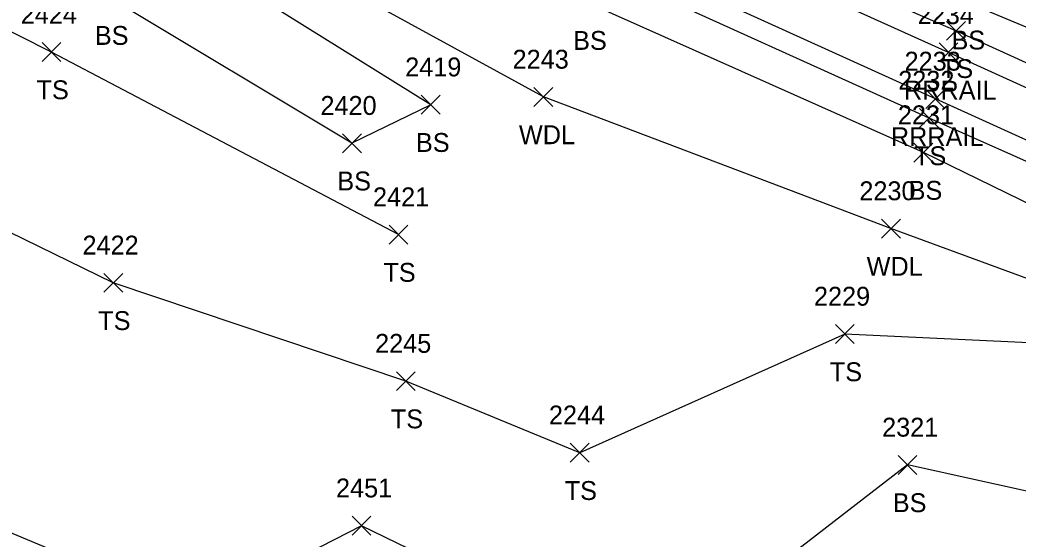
# Model space of a CAD drawing. Extents: x 1599569 to 1610055, y 642560 to 647860.
# Drawn here: x 1601397.5 to 1601503.2, y 647129.7 to 647184.7 of the extents above; entities that cross this region are included whole.
import ezdxf

# ---------------------------------------------------------------- set-up
doc = ezdxf.new("R2010")
doc.units = 0
for name, color, linetype in [('L_A', 7, 'Continuous'), ('L_I', 7, 'Continuous'), ('L_TIC', 7, 'Continuous'), ('LAWA', 7, 'Continuous'), ('LELB', 7, 'Continuous'), ('R_A', 7, 'Continuous'), ('R_I', 7, 'Continuous'), ('R_TIC', 7, 'Continuous'), ('RR', 7, 'Continuous')]:
    doc.layers.add(name, color=color, linetype=linetype)

msp = doc.modelspace()

# ---------------------------------------------------------------- linework, layer by layer
at = {"layer": 'L_TIC'}
for points in [[(1601495.65, 647182.57), (1601497.65, 647184.57)], [(1601497.65, 647182.57), (1601495.65, 647184.57)], [(1601399.83, 647180.32), (1601401.83, 647182.32)], [(1601401.83, 647180.32), (1601399.83, 647182.32)], [(1601440, 647174.74), (1601442, 647176.74)], [(1601442, 647174.74), (1601440, 647176.74)], [(1601440, 647174.74), (1601442, 647176.74)], [(1601442, 647174.74), (1601440, 647176.74)], [(1601451.94, 647175.56), (1601453.94, 647177.56)], [(1601453.94, 647175.56), (1601451.94, 647177.56)], [(1601492.8, 647173.33), (1601494.8, 647175.33)], [(1601494.8, 647173.33), (1601492.8, 647175.33)], [(1601431.66, 647170.66), (1601433.66, 647172.66)], [(1601433.66, 647170.66), (1601431.66, 647172.66)], [(1601492.2, 647169.67), (1601494.2, 647171.67)], [(1601494.2, 647169.67), (1601492.2, 647171.67)], [(1601436.59, 647160.98), (1601438.59, 647162.98)], [(1601438.59, 647160.98), (1601436.59, 647162.98)], [(1601488.77, 647161.62), (1601490.77, 647163.62)], [(1601490.77, 647161.62), (1601488.77, 647163.62)], [(1601406.37, 647155.87), (1601408.37, 647157.87)], [(1601408.37, 647155.87), (1601406.37, 647157.87)], [(1601483.88, 647150.45), (1601485.88, 647152.45)], [(1601485.88, 647150.45), (1601483.88, 647152.45)], [(1601437.37, 647145.46), (1601439.37, 647147.46)], [(1601439.37, 647145.46), (1601437.37, 647147.46)], [(1601455.79, 647137.87), (1601457.79, 647139.87)], [(1601457.79, 647137.87), (1601455.79, 647139.87)], [(1601490.52, 647136.58), (1601492.52, 647138.58)], [(1601492.52, 647136.58), (1601490.52, 647138.58)], [(1601432.67, 647130.14), (1601434.67, 647132.14)], [(1601434.67, 647130.14), (1601432.67, 647132.14)]]:
    msp.add_lwpolyline(points, dxfattribs=at)
at = {"layer": 'LAWA'}
msp.add_lwpolyline([(1601543.96, 647141.4), (1601525.42, 647149.53), (1601489.77, 647162.62), (1601452.94, 647176.56), (1601417.12, 647196.22), (1601382.92, 647211.21), (1601340.76, 647217.08), (1601306.6, 647220.69), (1601276.84, 647227.54)], dxfattribs=at)
at = {"layer": 'LELB'}
for points in [[(1601782.46, 647059.4), (1601738.77, 647079.33), (1601690.4, 647099.93), (1601647.7, 647120.25), (1601610.06, 647137.74), (1601571.92, 647154.07), (1601536.97, 647170.25), (1601497.74, 647186.59), (1601465.75, 647201.27), (1601394.71, 647231.37), (1601362.21, 647245.73), (1601329.86, 647260.18), (1601292.61, 647278.06)], [(1601779.91, 647055.75), (1601736.46, 647075.12), (1601688.29, 647096.71), (1601645.48, 647116.21), (1601608.08, 647132.73), (1601569.65, 647149.89), (1601535.69, 647165.81), (1601496.65, 647183.57), (1601464.02, 647197.75), (1601393.37, 647229.99), (1601361.18, 647244.46), (1601329.08, 647258.95), (1601292.39, 647275.61)], [(1601775.59, 647047.17), (1601732.38, 647067.08), (1601683.7, 647088.91), (1601643.36, 647107.34), (1601603.44, 647124.91), (1601567.99, 647141.64), (1601531.27, 647157.66), (1601493.8, 647174.33), (1601459.44, 647189.9), (1601386.61, 647223.07), (1601358.08, 647235.63), (1601326.17, 647250.65), (1601291.06, 647266.1)], [(1601773.31, 647043.55), (1601729.79, 647062.38), (1601680.12, 647084.11), (1601641.71, 647102.62), (1601602.29, 647120.48), (1601566.23, 647136.75), (1601528.31, 647153.55), (1601493.2, 647170.67), (1601457.65, 647186.55), (1601384.33, 647220.55), (1601356.62, 647233.9), (1601324.87, 647247.72), (1601290.33, 647262.4)], [(1601441, 647175.74), (1601414.25, 647192.43), (1601380.27, 647208.07), (1601340.76, 647217.08)], [(1601441, 647175.74), (1601432.66, 647171.66), (1601406.98, 647187.08), (1601375.36, 647201.94), (1601340.76, 647217.08)], [(1601437.59, 647161.98), (1601400.83, 647181.32), (1601369.9, 647196.94), (1601340.76, 647217.08)], [(1601525.42, 647149.53), (1601484.88, 647151.45), (1601456.79, 647138.87), (1601438.37, 647146.46), (1601407.37, 647156.87), (1601391.65, 647164.55), (1601361.3, 647186.25), (1601336.82, 647204.88)], [(1601786.42, 647020.74), (1601762.67, 647028.99), (1601751.67, 647030.89), (1601732.96, 647040.23), (1601698.47, 647053.93), (1601685.61, 647056.76), (1601664.03, 647070.39), (1601639.36, 647075.33), (1601612.31, 647092.93), (1601584.19, 647104.61), (1601538.73, 647126.26), (1601520.13, 647131.26), (1601491.52, 647137.58), (1601474.1, 647124.14), (1601450.02, 647123.17), (1601433.67, 647131.14), (1601416.15, 647122.17), (1601393.03, 647131.84), (1601363.94, 647128.32), (1601336.7, 647135.49), (1601311.97, 647149.61), (1601287.9, 647169.52)]]:
    msp.add_lwpolyline(points, dxfattribs=at)
at = {"layer": 'R_TIC'}
for points in [[(1601494.86, 647180.28), (1601496.86, 647182.28)], [(1601496.86, 647180.28), (1601494.86, 647182.28)], [(1601493.47, 647175.35), (1601495.47, 647177.35)], [(1601495.47, 647175.35), (1601493.47, 647177.35)]]:
    msp.add_lwpolyline(points, dxfattribs=at)
at = {"layer": 'RR'}
for points in [[(1601779.12, 647053.17), (1601735.09, 647073.16), (1601687.31, 647094.74), (1601644.71, 647114), (1601606.95, 647130.88), (1601569.09, 647148.12), (1601534.47, 647163.75), (1601495.86, 647181.28), (1601463.02, 647196.09), (1601391.8, 647228.12), (1601360.22, 647242.53), (1601328.26, 647256.93), (1601292.48, 647273.14)], [(1601776.78, 647048.8), (1601733.22, 647068.55), (1601684.48, 647090.67), (1601642.81, 647109.31), (1601604.47, 647126.66), (1601567.91, 647143.17), (1601532.13, 647159.27), (1601494.47, 647176.35), (1601460.57, 647191.75), (1601388.17, 647224.38), (1601357.5, 647238.3), (1601326.5, 647252.29), (1601291.28, 647268.22)]]:
    msp.add_lwpolyline(points, dxfattribs=at)

# ---------------------------------------------------------------- texts
at = {"layer": 'L_A'}
for s, p in [('BS', (1601405.42, 647182.08)), ('BS', (1601456.09, 647181.55)), ('BS', (1601496.18, 647181.59)), ('TS', (1601495.06, 647178.57)), ('TS', (1601399.24, 647176.32)), ('WDL', (1601450.35, 647171.56)), ('BS', (1601439.44, 647170.74)), ('BS', (1601439.44, 647170.74)), ('TS', (1601492.21, 647169.33)), ('BS', (1601431.11, 647166.66)), ('BS', (1601491.64, 647165.67)), ('TS', (1601435.99, 647156.98)), ('WDL', (1601487.19, 647157.62)), ('TS', (1601405.78, 647151.87)), ('TS', (1601483.29, 647146.45)), ('TS', (1601436.78, 647141.46)), ('TS', (1601455.2, 647133.87)), ('BS', (1601489.96, 647132.58))]:
    msp.add_text(s, height=2, dxfattribs=at).set_placement(p)
at = {"layer": 'L_I'}
for s, p in [('2424', (1601397.57, 647184.32)), ('2243', (1601449.68, 647179.56)), ('2419', (1601438.3, 647178.74)), ('2419', (1601438.3, 647178.74)), ('2232', (1601490.54, 647177.33)), ('2420', (1601429.32, 647174.66)), ('2231', (1601490.5, 647173.67)), ('2230', (1601486.42, 647165.62)), ('2421', (1601434.89, 647164.98)), ('2422', (1601404.11, 647159.87)), ('2229', (1601481.61, 647154.45)), ('2245', (1601435.11, 647149.46)), ('2244', (1601453.53, 647141.87)), ('2321', (1601488.83, 647140.58)), ('2451', (1601430.97, 647134.14))]:
    msp.add_text(s, height=2, dxfattribs=at).set_placement(p)
at = {"layer": 'R_A'}
for p in [(1601491.15, 647176.28), (1601489.76, 647171.35)]:
    msp.add_text('RRRAIL', height=2, dxfattribs=at).set_placement(p)
at = {"layer": 'R_I'}
for s, p in [('2234', (1601492.6, 647184.28)), ('2233', (1601491.21, 647179.35))]:
    msp.add_text(s, height=2, dxfattribs=at).set_placement(p)

doc.saveas('drawing.dxf')
